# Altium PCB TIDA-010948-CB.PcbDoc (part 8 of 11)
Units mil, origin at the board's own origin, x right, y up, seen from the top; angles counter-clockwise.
Board outline 8100 x 8400 mil, 8 copper layers (L01 - TOP, L02 - GND, L03 - SIG, L04 - GND, L05 - PWR, L06 - SIG, L07 - GND, L08 - BOTTOM), stack 59.656 mil thick; 711 components, 572 nets, 2646 pads, 1325 vias.
Unrouted connection lines stored in the file: 988.
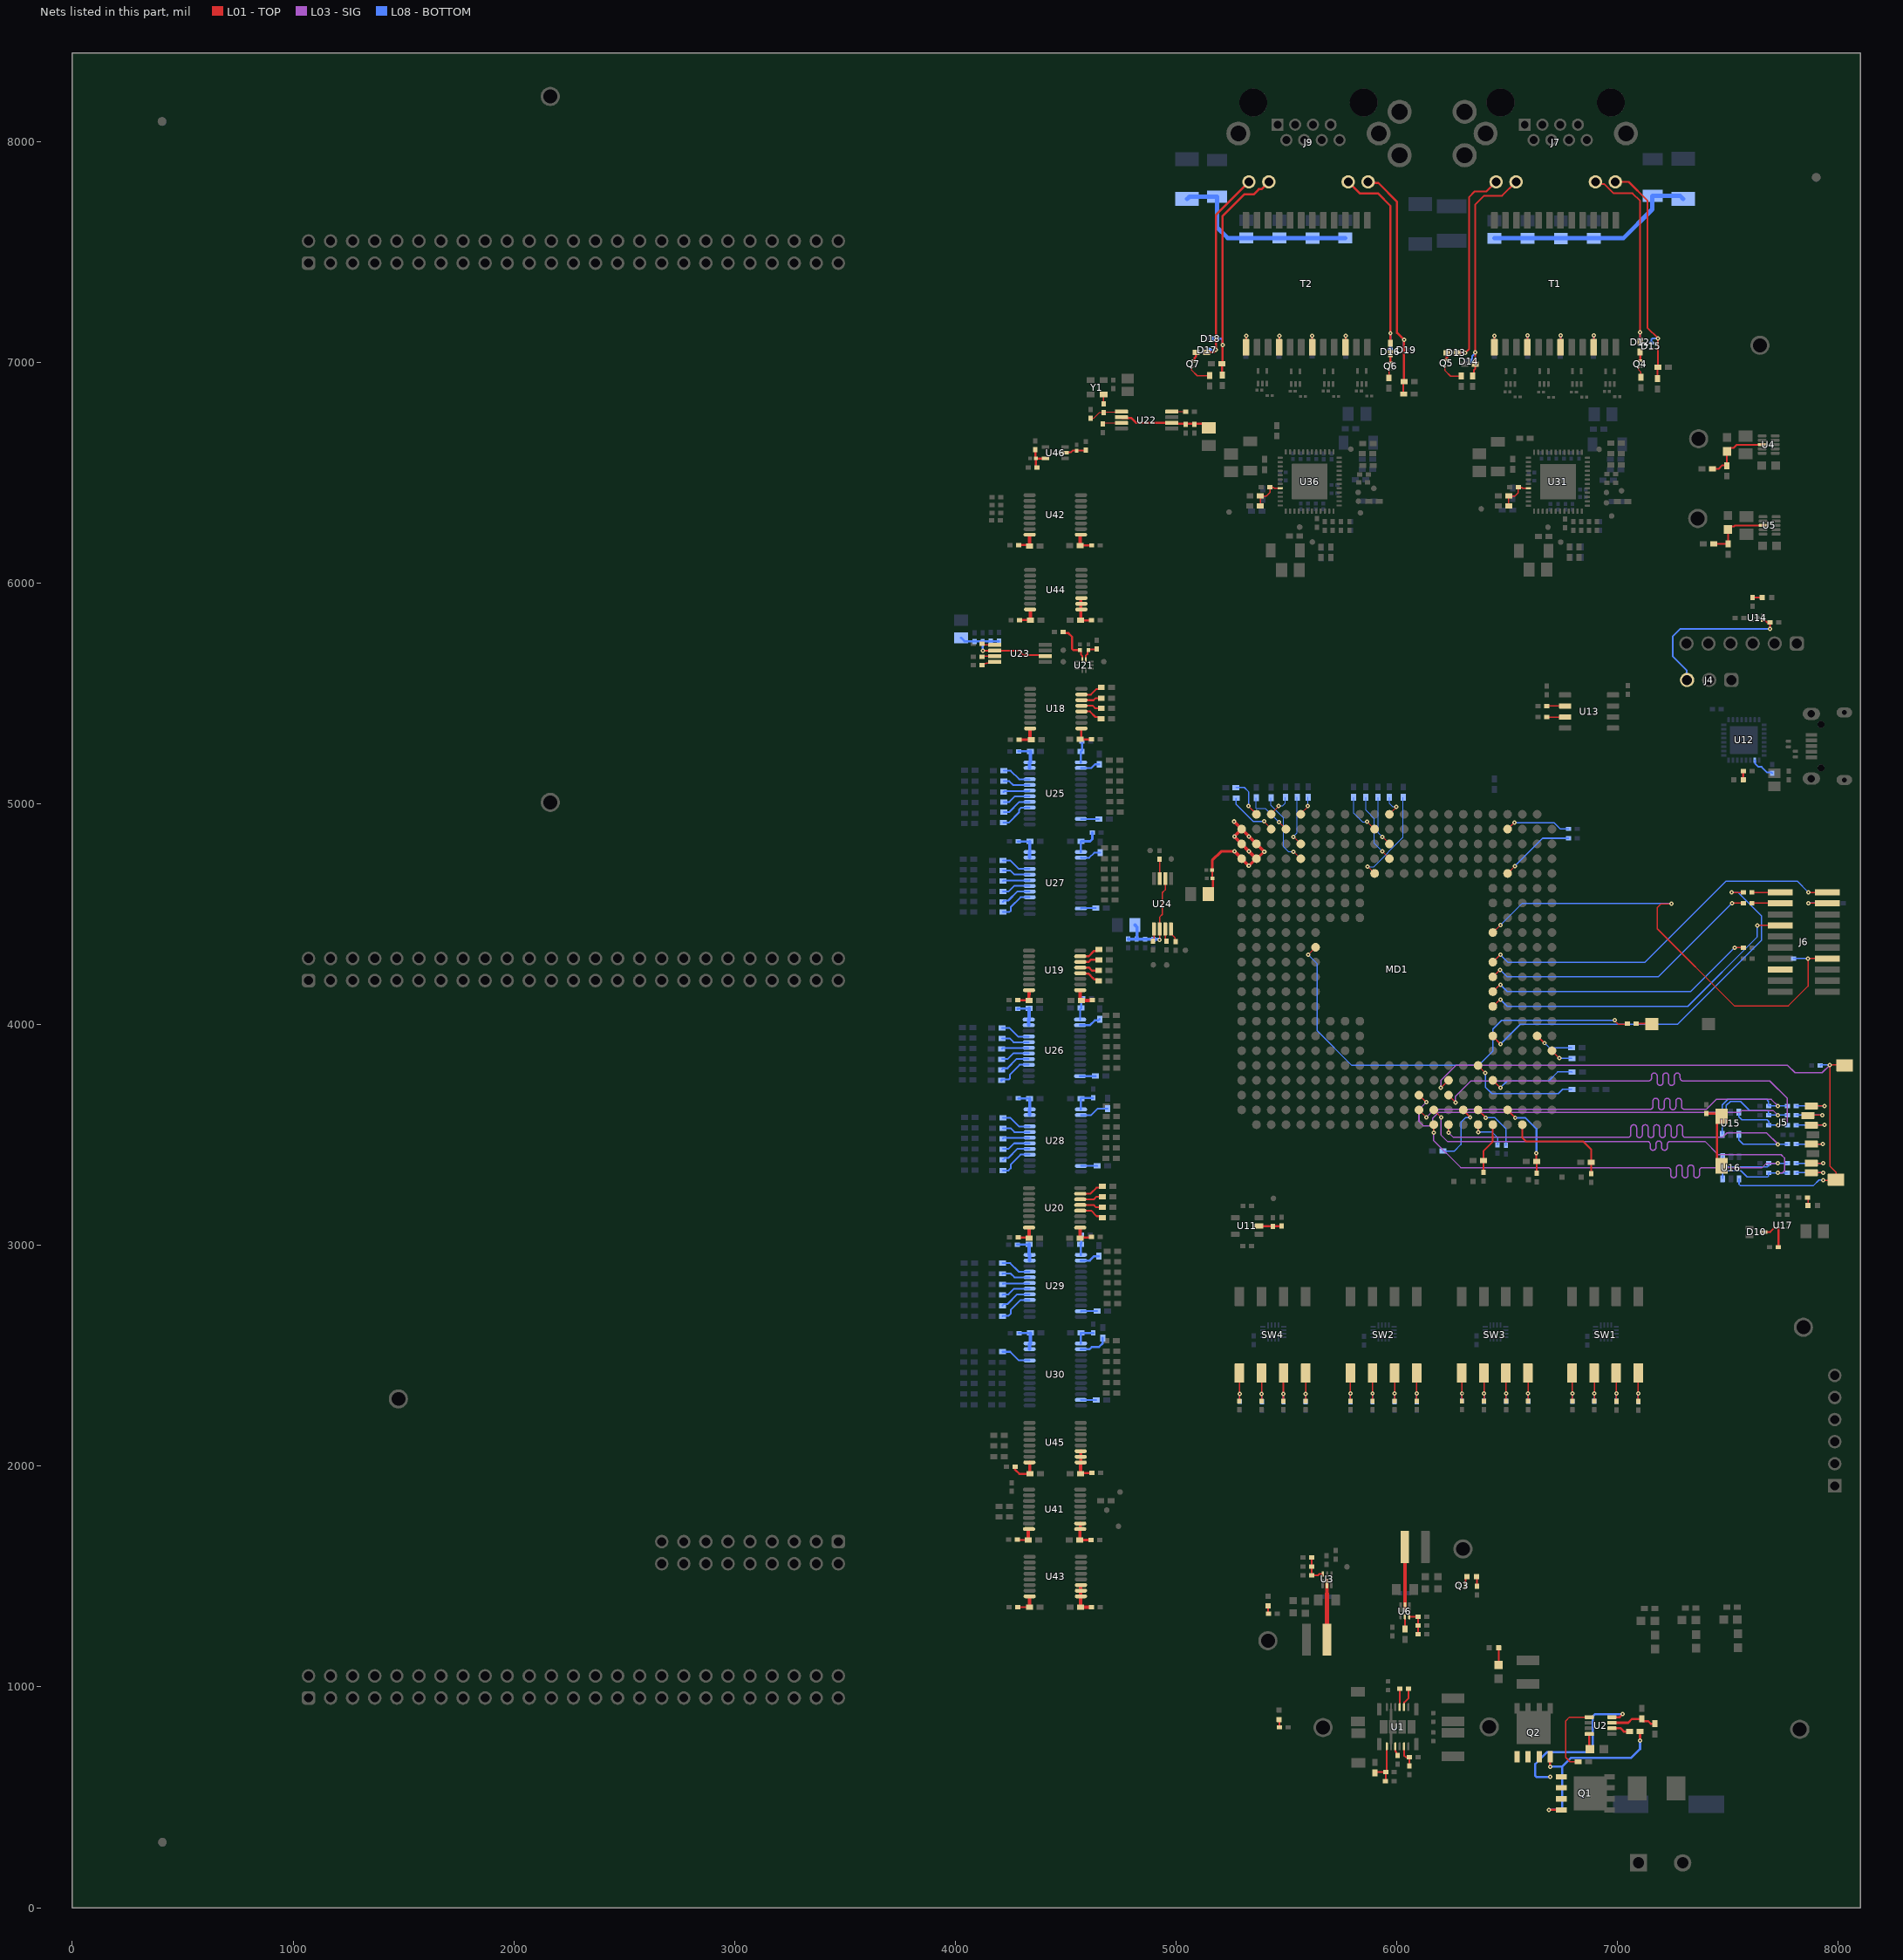
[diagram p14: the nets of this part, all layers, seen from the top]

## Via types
v1: diameter 19.68, hole 7.87, L01 - TOP to L08 - BOTTOM, 1310 vias
v2: diameter 20, hole 7.87, L01 - TOP to L08 - BOTTOM, tented both sides, 7 vias
v3: diameter 200, hole 144, L01 - TOP to L08 - BOTTOM, 6 vias
v4: diameter 20, hole 8, L01 - TOP to L08 - BOTTOM, tented both sides, 2 vias

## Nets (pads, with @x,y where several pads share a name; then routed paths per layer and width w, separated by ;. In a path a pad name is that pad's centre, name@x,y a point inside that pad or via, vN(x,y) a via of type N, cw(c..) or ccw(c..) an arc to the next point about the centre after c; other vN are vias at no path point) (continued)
JTAG_EMU1: J6.14 MD1.J18 R87.1 | length 2164.5
  L01 - TOP w6: MD1.J18@6435.04,4416.92 6435.48,4416.92 6469.56,4451 v1(6470,4451) ; v1(7244,4547) 7197,4547 7180,4530 7180,4434 7529,4085 7774,4085 7863,4174 v1(7863,4299) J6.14@7950.5,4299
  L08 - BOTTOM w6: v1(6470,4451) 6567,4548 v1@7235,4548 ; R87.1@7796.68,4299 v1(7863,4299)
JTAG_EMU_RSTn: J6.15
JTAG_TDI: J6.3 R93.2 | length 129.2
  L01 - TOP w5: R93.2@7608.69,4550 7736.5,4550 J6.3@7737.5,4549
JTAG_TDIS: J6.4 R84.2 | length 203.2
  L01 - TOP w5: v1(7865,4550) 7949.5,4550 J6.4@7950.5,4549
  L08 - BOTTOM w5: v1(7865,4550) R84.2@7982.31,4550
JTAG_TDO: J6.7 MD1.P18 | length 1510.9
  L01 - TOP w6: MD1.P18@6435.04,4082.28 6436.16,4082.28 6467.88,4114 v1(6469,4114) ; v1(7633,4449) J6.7@7737.5,4449
  L08 - BOTTOM w6: v1(6469,4114) 6500.5,4082.5 7318.5,4082.5 7633,4397 v1(7633,4449)
JTAG_TMS: J6.1 R94.2 | length 128.8
  L01 - TOP w6: R94.2@7608.69,4599 J6.1@7737.5,4599
JTAG_TRST#: J6.2 MD1.L18 | length 1716.3
  L01 - TOP w6: MD1.L18@6435.04,4283.06 6435.55,4283.06 6468.49,4316 v1(6469,4316) ; v1(7865,4599) J6.2@7950.5,4599
  L08 - BOTTOM w6: v1(6469,4316) 6502.5,4282.5 7124.5,4282.5 7492,4650 7814,4650 v1(7865,4599)
MMC1_CLK: MD1.AB15 R79.1 U15.4 | length 2289.2
  L01 - TOP w6: MD1.AB15@6234.25,3546.84 6234.63,3546.47 6234.63,3510.37 v1(6235,3510)
  L03 - SIG w6: v1(6235,3510) 6256,3489 7044.25,3489 7047.25,3489 ccw(c7047.25,3502) 7060.25,3502 7060.25,3533.37 cw(c7073.25,3533.37) 7086.25,3533.37 7086.25,3501.37 ccw(c7099.25,3501.37) 7112.25,3501.37 7112.25,3533.37 cw(c7125.25,3533.37) 7138.25,3533.37 7138.25,3501.37 ccw(c7151.25,3501.37) 7164.25,3501.37 7164.25,3533.37 cw(c7177.25,3533.37) 7190.25,3533.37 7190.25,3501.37 ccw(c7203.25,3501.37) 7216.25,3501.37 7216.25,3533.37 cw(c7229.25,3533.37) 7242.25,3533.37 7242.25,3501.37 ccw(c7255.25,3501.37) 7268.25,3501.37 7268.25,3533.37 cw(c7281.25,3533.37) 7294.25,3533.37 7294.25,3502 ccw(c7307.25,3502) 7307.25,3489 7369,3489 7475,3489 7496,3510 7675,3510 v1(7727,3458)
  L08 - BOTTOM w5: U15.4@7549.4,3502.8 7549.4,3478.6 7570,3458 v1(7727,3458) 7769.32,3458 R79.1@7770.32,3459
MMC1_CMD: MD1.Y15 R70.1 R78.1 U15.3 | length 2289.6
  L01 - TOP w6: MD1.Y15@6234.25,3680.7 6234.25,3679.23 6266,3647.48 v1(6266,3646)
  L03 - SIG w6: v1(6266,3646) 6266,3675.5 6335.5,3745 7137.62,3745 7140.62,3745 ccw(c7140.62,3758) 7153.62,3758 7153.62,3767.46 cw(c7166.62,3767.46) 7179.62,3767.46 7179.62,3737.78 ccw(c7192.62,3737.78) 7205.62,3737.78 7205.62,3767.46 cw(c7218.62,3767.46) 7231.62,3767.46 7231.62,3737.78 ccw(c7244.62,3737.78) 7257.62,3737.78 7257.62,3767.46 cw(c7270.62,3767.46) 7283.62,3767.46 7283.62,3758 ccw(c7296.62,3758) 7296.62,3745 7326,3745 7689.78,3745 7769.32,3665.46 7769.32,3560.75 7753.57,3545 v1(7726,3545)
  L08 - BOTTOM w5: U15.3@7549.4,3603.2 7549.4,3582.6 7564,3568 7678,3568 7685,3561 7685,3545.31 R70.1@7684.68,3545
  L08 - BOTTOM w6: R70.1@7684.68,3545 v1(7726,3545) R78.1@7769.32,3545
MMC1_DAT0: MD1.AB14 R71.1 R80.1 U16.1 | length 2290.9
  L01 - TOP w6: v1(6167,3510) 6167.16,3510.16 6167.16,3546.68 MD1.AB14@6167.32,3546.84
  L03 - SIG w6: v1@6164.38,3507.38 v1(6167,3510) 6167,3475 6289.98,3352.02 7166.52,3352.02 7228,3352.02 cw(c7228,3339.02) 7241,3339.02 7241,3319.44 ccw(c7254,3319.44) 7267,3319.44 7267,3351.3 cw(c7280,3351.3) 7293,3351.3 7293,3319.44 ccw(c7306,3319.44) 7319,3319.44 7319,3351.3 cw(c7332,3351.3) 7345,3351.3 7345,3319.44 ccw(c7358,3319.44) 7371,3319.44 7371,3339.02 cw(c7384,3339.02) 7384,3352.02 7387,3352.02 7655.02,3352.02 7675,3372 v1(7726,3372)
  L08 - BOTTOM w5: U16.1@7475.6,3402.2 7475.6,3378.4 7499.34,3354.66 7678.66,3354.66 7685,3361 7685,3371.69 R71.1@7684.68,3372
  L08 - BOTTOM w6: R71.1@7684.68,3372 v1(7726,3372) R80.1@7769.32,3372
MMC1_DAT1: MD1.AA14 R72.1 R81.1 U16.6 | length 2289.6
  L01 - TOP w6: MD1.AA14@6167.32,3613.73 v1(6201,3580)
  L03 - SIG w6: v1(6201,3580) 6201,3499 6229,3471 7074,3471 7134.85,3471 cw(c7134.85,3458) 7147.85,3458 7147.85,3443.68 ccw(c7160.85,3443.68) 7173.85,3443.68 7173.85,3459.69 cw(c7186.85,3459.69) 7199.85,3459.69 7199.85,3443.68 ccw(c7212.85,3443.68) 7225.85,3443.68 7225.85,3458 cw(c7238.85,3458) 7238.85,3471 7241.85,3471 7396,3471 7456,3411 7741,3411 7756,3396 7756,3338 7746,3328 v1(7726,3328)
  L08 - BOTTOM w5: U16.6@7475.6,3301.8 7475.6,3329.6 7483,3337 7560,3337 7587,3310 7680.07,3310 7683,3312.93 7683,3326.31 R72.1@7684.68,3328
  L08 - BOTTOM w6: R72.1@7684.68,3328 v1(7726,3328) R81.1@7769.32,3328
MMC1_DAT2: MD1.AA13 R68.1 R74.1 U15.1 | length 2289
  L01 - TOP w6: MD1.AA13@6100.39,3613.77 6100.39,3613.69 6134,3580.08 v1(6134,3580)
  L03 - SIG w6: v1(6134,3580) 6170,3616 7144,3616 7147,3616 ccw(c7147,3629) 7160,3629 7160,3653.24 cw(c7173,3653.24) 7186,3653.24 7186,3627.41 ccw(c7199,3627.41) 7212,3627.41 7212,3653.24 cw(c7225,3653.24) 7238,3653.24 7238,3627.41 ccw(c7251,3627.41) 7264,3627.41 7264,3653.24 cw(c7277,3653.24) 7290,3653.24 7290,3629 ccw(c7303,3629) 7303,3616 7369.62,3616 7402,3616 7447,3661 7697,3661 v1(7726,3632)
  L08 - BOTTOM w5: U15.1@7474.6,3603.2 7474.6,3636.6 7500,3662 7675,3662 7684.68,3652.31 R68.1@7684.68,3632
  L08 - BOTTOM w6: R68.1@7684.68,3632 v1(7726,3632) R74.1@7769.32,3632
MMC1_DAT3: MD1.Y13 R69.1 R76.1 U15.6 | length 2289.3
  L01 - TOP w6: MD1.Y13@6100.39,3680.7 6101.35,3680.7 6133.05,3649 v1(6134,3649)
  L03 - SIG w6: v1(6134,3649) 6100.39,3615.39 6100.39,3560.61 6120,3541 6147,3541 6162,3556 6162,3574.73 6189.27,3602 7554.7,3602 7563.7,3611 7705,3611 v1(7726,3590)
  L08 - BOTTOM w5: U15.6@7474.6,3502.8 7474.6,3558.86 7492.93,3577.19 7492.93,3633.93 7511,3652 7557,3652 7598,3611 7680,3611 7684.68,3606.31 R69.1@7684.68,3590
  L08 - BOTTOM w6: R69.1@7684.68,3590 v1(7726,3590) R76.1@7769.32,3590
NetC9_1: C9.1 R3.1 R6.2 U1.10 | length 210.1
  L01 - TOP w8: R3.1@5901,610.38 5905.62,615 C9.1@5949.31,615 ; R6.2@5949.31,573 C9.1@5949.31,615 ; U1.10@5954.26,730.83 5953.34,729.91 5953.34,619.02 C9.1@5949.31,615
NetC11_2: C11.2 U2.4 | length 68.7
  L01 - TOP w8: U2.4@6871.82,786.61 6871.82,721.69 C11.2@6874.5,719
NetC14_2: C14.2 R16.1 R17.2 U3.3 | length 128.4
  L01 - TOP w8: C14.2@5614.69,1582.5 5614.69,1542 R17.2@5614.69,1506 5643.96,1506 5649.55,1511.59 U3.3@5664.31,1511.59
NetC16_2: C16.2 R15.1 R18.2 U4.8 | length 308.9
  L01 - TOP w8: R15.1@7430.22,6517.26 7458.6,6517.26 7474.6,6533.26 7494.22,6533.26 R18.2@7495.6,6531.89 7495.6,6594.77 C16.2@7496.6,6595.77 7496.6,6596.56 7511.3,6611.26 7524.6,6611.26 7538.6,6625.26 7653.07,6625.26 U4.8@7655.07,6627.26
NetC23_2: C23.2 R20.1 R23.2 U5.8 | length 299.8
  L01 - TOP w8: R20.1@7436.23,6178.05 7500.23,6178.05 R23.2@7501.61,6176.67 7501.61,6240.55 C23.2@7499.61,6242.55 7514.1,6257.05 7527.61,6257.05 7531.61,6261.05 U5.8@7659.08,6261.05
NetC25_2: C25.2 R24.1 R25.2 U6.3 | length 119.3
  L01 - TOP w8: U6.3@6056.69,1318.41 6056.89,1318.2 6096.11,1318.2 R25.2@6096.31,1318 ; C25.2@6096.81,1238.5 R25.2@6096.81,1318
NetC29_1: C29.1 R59.2 U11.2 | length 104
  L01 - TOP w10: U11.2@5376.13,3088 5376.98,3087.16 5437.16,3087.16 C29.1@5438,3086.31 5438.5,3086.81 5478.5,3086.81 R59.2@5479,3087.31
NetC40_1: C40.1 J4.3 U14.1 | length 747.7
  L01 - TOP w8: U14.1@7654.13,5830.41 7667.59,5830.41 7677,5821 7690.32,5821 C40.1@7690.66,5821.34 ; v1(7690,5793) 7690.66,5793.66 C40.1@7690.66,5821.34 ; C40.1@7691.32,5822 C40.1@7690.66,5821.34
  L08 - BOTTOM w8: J4.3@7315,5561 7312.52,5563.48 7312.52,5605.48 7251,5667 7251,5759 7285,5793 v1(7690,5793)
NetC41_2: C41.2 MD1.AB20 R77.2 | length 503.9
  L01 - TOP w8: MD1.AB20@6568.9,3546.84 6568.9,3486.77 6584.67,3471 6844.06,3471 6880.62,3434.44 C41.2@6880.62,3377 6881,3376.62 R77.2@6881,3324.19
NetC42_2: C42.2 MD1.AA19 R75.2 | length 371
  L01 - TOP w8: MD1.AA19@6501.97,3613.77 6501.97,3612.4 6536,3578.37 v1(6536,3577) ; v1(6632.63,3417.31) 6632.63,3381.69 6633.63,3380.69 R75.2@6633.63,3327
  L08 - BOTTOM w8: v1@6534.63,3575.63 v1(6536,3577) 6583.15,3577 6632.75,3527.4 6632.75,3417.43 v1(6632.63,3417.31)
NetC43_2: C43.2 MD1.AB18 R73.2 | length 234.5
  L01 - TOP w8: R73.2@6392,3330.19 6392,3384.88 C43.2@6392.12,3385 6392.12,3426.62 6435.04,3469.54 MD1.AB18@6435.04,3546.84
NetC47_2: C47.2 R241.1 U18.1 | length 95.7
  L01 - TOP w10: C47.2@4566.12,5291.5 4566.87,5292.25 4615.56,5292.25 R241.1@4616.31,5293 ; C47.2@4571.14,5296.52 U18.1@4571.14,5341.43
NetC48_1: C48.1 R268.1 U18.16 | length 101
  L01 - TOP w12: R268.1@4289.69,5289.5 4289.94,5289.75 4343.13,5289.75 C48.1@4343.38,5290
  L01 - TOP w15: C48.1@4338.86,5294.31 U18.16@4338.86,5341.43
NetC49_2: C49.2 R276.1 U19.1 | length 96.9
  L01 - TOP w15: U19.1@4565.72,4155.51 4565.72,4113.8 C49.2@4570.3,4109.22 ; C49.2@4570.72,4109.65 R276.1@4619.46,4109.65
NetC50_1: C50.1 R281.1 U19.16 | length 98.7
  L01 - TOP w10: R281.1@4282.69,4111 4283.69,4110 4332.88,4110 4333.63,4109.25 C50.1@4333.88,4109
  L01 - TOP w15: C50.1@4333.63,4109.25 U19.16@4333.86,4155.93
NetC51_2: C51.2 R291.1 U20.1 | length 100.7
  L01 - TOP w10: C51.2@4565.08,3033 4565.61,3033.54 4567.32,3035.25 4614.57,3035.25 R291.1@4616.81,3037.5
  L01 - TOP w15: C51.2@4565.61,3033.54 4565.61,3079.9 U20.1@4566.14,3080.43
NetC52_1: C52.1 R317.1 U20.16 | length 100.2
  L01 - TOP w10: R317.1@4284.19,3037 4286.44,3034.75 4332.63,3034.75 4334.37,3033.01 C52.1@4334.88,3032.5
  L01 - TOP w15: U20.16@4333.86,3080.43 4334.37,3079.92 C52.1@4334.37,3033.01
NetC53_1: C53.1 C54.1 L3.1 U22.2 U22.6 | length 415.5
  L01 - TOP w10: U22.2@4752.33,6750.8 4755.08,6748.04 4796.85,6748.04 4819.69,6725.2 U22.6@4980.67,6725.2 4984.38,6721.5 5129.5,6721.5 L3.1@5148,6703
NetC55_1: C55.1 R318.1 U21.7 | length 190.3
  L01 - TOP w8: C55.1@4564.5,5696.01 4568.77,5691.74 4568.77,5676.23 4574.71,5670.29 4574.71,5651.82 U21.7@4574.77,5651.76
  L01 - TOP w10: R318.1@4488.19,5777.5 4493.03,5772.66 4512.34,5772.66 4529,5756 4529,5701.87 4534.86,5696.01 C55.1@4564.5,5696.01
NetC56_2: C56.2 R319.1 U21.6 | length 88.6
  L01 - TOP w8: U21.6@4590.52,5651.76 4590.58,5651.82 4590.58,5670.08 4598.73,5678.23 4598.73,5691.74 C56.2@4603,5696.01 4605.65,5698.66 4637.35,5698.66 R319.1@4640,5701.31
NetC59_1: C59.1 C60.1 C61.1 C62.1 L4.1 U23.2 U23.6 | length 510.9
  L01 - TOP w8: v1(4124,5694) 4124.15,5694.15 4178.68,5694.15 U23.6@4178.83,5694.3 4287.2,5694.3 4308.5,5673 4402.88,5673 U23.2@4407.17,5668.7
  L08 - BOTTOM w8: v1(4124,5694) v1(4124,5694) 4123.96,5732.78 C61.1@4124,5732.81
  L08 - BOTTOM w10: L4.1@4026,5752 4041.69,5736.31 4086.5,5736.31 4121.75,5736.31 C62.1@4159.77,5736.31 ; C62.1@4159.77,5736.46 C59.1@4197.65,5736.46
NetC63_1: C63.1 C64.1 C65.1 C66.1 L5.1 U24.2 U24.6 | length 491.9
  L01 - TOP w6: v1(4925.5,4384.5) 4925.35,4384.65 4925.35,4432.68 U24.6@4925.2,4432.83 4925.5,4433.12 4925.5,4486.5 4938,4499 4938,4598 4950.8,4610.8 U24.2@4950.8,4661.17
  L08 - BOTTOM w15: C64.1@4784.54,4387.09 4784.75,4386.88 4860.64,4386.88 C66.1@4860.85,4386.66 ; L5.1@4814,4450.5 4823.2,4441.3 C65.1@4823.2,4387.38 ; C66.1@4865.16,4386.33 4922.4,4386.33 4924.23,4384.5 v1(4925.5,4384.5)
NetC79_2: C79.2 R322.1 U25.1 | length 96.2
  L08 - BOTTOM w10: U25.1@4569.14,5187.75 4569.14,5237.02 C79.2@4570.12,5238 4573.76,5241.64 R322.1@4573.76,5282.03
NetC80_2: C80.2 R320.1 U26.1 | length 103.2
  L08 - BOTTOM w8: U26.1@4565.14,4022.75 4565.14,4070.02 C80.2@4570.12,4075
  L08 - BOTTOM w10: C80.2@4570.12,4075 R320.1@4570.12,4113.08 ; R320.1@4570.15,4113.11 4570.15,4115.08 4575,4119.92 R320.1@4576.96,4119.92
NetC93_2: C93.2 R326.1 U27.1 | length 134
  L08 - BOTTOM w10: U27.1@4569.14,4781.83 4569.14,4829.55 C93.2@4569.78,4830.19 4610.69,4830.19 4620.81,4840.31 R326.1@4620.81,4870.5
NetC94_2: C94.2 R324.1 U28.1 | length 107
  L08 - BOTTOM w10: U28.1@4569.14,3615.75 4569.14,3664.98 C94.2@4568.62,3665.5 4570.03,3666.91 4623.09,3666.91 R324.1@4624.5,3668.31
NetC101_2: C101.2 R328.1 U29.1 | length 92.9
  L08 - BOTTOM w10: U29.1@4569.14,2957.25 4569.14,3003.37 C101.2@4567.3,3005.21 4570.98,3008.9 R328.1@4570.98,3047.9
NetC108_2: C108.2 R330.1 U30.1 | length 103.3
  L08 - BOTTOM w10: U30.1@4569.14,2555.75 4569.14,2602.54 C108.2@4569.71,2603.11 4570,2603.4 4624.9,2603.4 R330.1@4625.19,2603.68
NetC112_1: C112.1 R323.1 U25.23 U25.24 | length 131
  L08 - BOTTOM w10: R323.1@4286.19,5237.5 4286.44,5237.25 4339.63,5237.25 C112.1@4339.88,5237
  L08 - BOTTOM w15: U25.23@4336.86,5162.16 U25.24@4336.86,5187.75 4338.62,5187.75 4339.88,5189 C112.1@4339.88,5237
NetC120_1: C120.1 R321.1 U26.23 U26.24 | length 129.4
  L08 - BOTTOM w10: R321.1@4282.19,4071.5 4282.94,4072.25 4333.63,4072.25 C120.1@4334.38,4073
  L08 - BOTTOM w15: U26.23@4332.86,3997.16 U26.24@4332.86,4022.75 4333.12,4022.75 4334.38,4024 C120.1@4334.38,4073
NetC126_1: C126.1 R327.1 U27.23 U27.24 | length 125.9
  L08 - BOTTOM w10: R327.1@4284.69,4830 4284.93,4829.75 4336.61,4829.75 C126.1@4337.15,4829.22
  L08 - BOTTOM w15: U27.23@4336.86,4756.24 U27.24@4336.86,4781.83 4337.15,4782.12 C126.1@4337.15,4829.22
NetC132_1: C132.1 R325.1 U28.23 U28.24 | length 126.6
  L08 - BOTTOM w10: R325.1@4285.69,3666 4286.13,3665.56 4336.46,3665.56 C132.1@4336.9,3665.11
  L08 - BOTTOM w15: U28.23@4336.84,3590.18 4336.84,3615.73 U28.24@4336.86,3615.75 C132.1@4336.9,3665.11
NetC133_1: C133.1 T1.1 | length 96
  L01 - TOP w8: T1.1@6442,7067.5 6442.5,7068 v1(6442.5,7120.5)
  L08 - BOTTOM w8: C133.1@6441.5,7078.12 6442,7078.62 6442,7120 v1(6442.5,7120.5)
NetC134_1: C134.1 T1.4 | length 97.3
  L01 - TOP w8: T1.4@6592,7067.5 6592.5,7068 v1(6592.5,7121)
  L08 - BOTTOM w8: C134.1@6592,7077.62 6592.25,7077.87 6592.25,7120.75 v1(6592.5,7121)
NetC136_2: C136.2 D14.2 J7.10 R240.1 | length 1055.9
  L01 - TOP w8: R240.1@6343,6937.12 6349.87,6943.99 6349.87,6964.87 6355.5,6970.5 6355.5,6990.62 C136.2@6354.62,6991.5 6354.62,7713.62 6395,7754 6477.07,7754 J7.10@6540.08,7817.01
  L08 - BOTTOM w8: D14.2@6339.8,7005 6341.97,7007.18 6341.97,7028.81 6354.5,7041.34 v1(6354.5,7044.5)
NetC137_1: C137.1 T1.7 | length 96.3
  L01 - TOP w8: T1.7@6742,7067.5 v1(6742,7121)
  L08 - BOTTOM w8: C137.1@6741,7078.62 6741.5,7079.12 6741.5,7120.5 v1(6742,7121)
NetC138_1: C138.1 R246.2 R305.2 U31.20 | length 166
  L01 - TOP w6: R305.2@6506.69,6349.06 R305.2@6507.12,6349.5 ; R305.2@6506.98,6349.53 6506.98,6394.03 6535.03,6394.03 6550.04,6409.04 6550.04,6433.03 6565.79,6433.03 6569.35,6429.47 U31.20@6596.14,6429.47
NetC139_2: C139.2 D15.2 J7.12 R244.2 | length 1055.9
  L01 - TOP w8: J7.12@6990.08,7817.01 7050.49,7817.01 7135,7732.5 7135,7156.5 v1(7183.38,7108.12) C139.2@7183.38,6977.5 7181.5,6975.62 R244.2@7181.5,6926.62
  L08 - BOTTOM w8: D15.2@7153,7086.5 7153,7103.44 7157.69,7108.12 v1(7183.38,7108.12)
NetC140_1: C140.1 T1.10 | length 97.6
  L01 - TOP w8: T1.10@6892,7067.5 v1(6892,7121)
  L08 - BOTTOM w8: C140.1@6891.5,7077.12 6891.75,7077.37 6891.75,7120.75 v1(6892,7121)
NetC141_1: C141.1 R229.2 R231.2 R245.2 R248.2 R249.2 | length 974.7
  L08 - BOTTOM w20: R229.2@6443,7561.5 7026,7561.5 7157,7692.5 7157,7752.32 C141.1@7159,7754.32 7283.13,7754.32 R249.2@7297,7740.45
NetC154_1: C154.1 R329.1 U29.23 U29.24 | length 130.2
  L08 - BOTTOM w10: R329.1@4280.19,3003 4281.22,3004.04 4333.02,3004.04 C154.1@4334.06,3005.08
  L08 - BOTTOM w15: C154.1@4334.06,3005.08 4334.06,2958.5 4335.32,2957.25 U29.24@4336.86,2957.25 U29.23@4336.86,2931.66
NetC162_1: C162.1 R331.1 U30.23 U30.24 | length 127
  L08 - BOTTOM w10: R331.1@4288.19,2602.5 4288.44,2602.75 4339.63,2602.75 C162.1@4339.88,2603
  L08 - BOTTOM w15: U30.23@4336.86,2530.16 U30.24@4336.86,2555.75 4338.62,2555.75 4339.88,2557 C162.1@4339.88,2603
NetC168_1: C168.1 C174.1 L12.1 MD1.B1 MD1.C1 MD1.C2 MD1.D1 MD1.D2 | length 853.4
  L01 - TOP w8: C174.1@5163.49,4700 5164.22,4699.27 5164.22,4663.27 C168.1@5164.95,4662.54 ; v2@5263,4919.84 v2(5263,4920)
  L01 - TOP w10: L12.1@5146.5,4590.5 5166.5,4610.5 5166.5,4645.58 5167.71,4646.79 5167.71,4659.78 C168.1@5164.95,4662.54
  L01 - TOP w12: C174.1@5163.49,4700 5163.49,4743.74 5204.01,4784.26 v2(5265,4784.26) ; v2(5329,4720) 5330.8,4720 5362.37,4751.57 MD1.D2@5364.17,4751.57 5366.4,4751.57 5397.84,4783 v2(5400,4783)
  L01 - TOP w15: v2(5263,4920) v2(5400,4783) ; v2(5265,4784.26) 5265,4784.13 5329,4720.13 v2(5329,4720) ; MD1.B1@5297.24,4885.43 5297.24,4885.34 5264,4852.09 v4(5264,4852) 5264,4851.87 5364.17,4751.7 MD1.D2@5364.17,4751.57
  L01 - TOP w20: v4@5264,4851.74 v4@5264,4851.87 ; v2@5330.49,4785.25 v2@5330.71,4785.03
  other v2: 5330.27,4785.03
  other v4: 5330.27,4851.96
NetC175_1: C175.1 T2.1 | length 92.7
  L01 - TOP w8: T2.1@5317,7067.5 5318,7068.5 v1(5318,7119)
  L08 - BOTTOM w8: C175.1@5317,7078.62 5317.5,7079.12 5317.5,7118.5 v1(5318,7119)
NetC176_1: C176.1 T2.4 | length 92.7
  L01 - TOP w8: T2.4@5467,7067.5 5468,7068.5 v1(5468,7119)
  L08 - BOTTOM w8: C176.1@5467,7078.62 5467.5,7079.12 5467.5,7118.5 v1(5468,7119)
NetC178_2: C178.2 D18.2 J9.10 R280.1 | length 1064.8
  L01 - TOP w10: C178.2@5207.12,6994 5210.12,6997 5210.12,7661.12 5309,7760 5351,7760 5375,7784 5387.07,7784 J9.10@5420.08,7817.01 ; R280.1@5209,6941.12 C178.2@5209,6994
  L08 - BOTTOM w10: D18.2@5169.22,7106.61 5204.64,7106.61 5210.5,7100.75 v1(5210.5,7078) v1@5207.88,7078
NetC179_1: C179.1 T2.7 | length 89.9
  L01 - TOP w8: T2.7@5617,7067.5 v1(5617,7119)
  L08 - BOTTOM w8: C179.1@5617,7080.62 v1(5617,7119)
NetC180_1: C180.1 R260.2 R286.2 U36.20 | length 166.8
  L01 - TOP w6: R260.2@5381.12,6349 5382.12,6350 R286.2@5382.12,6394.5 5410.18,6394.5 5425.19,6409.51 C180.1@5425.19,6433.5 5440.93,6433.5 5444.49,6429.94 U36.20@5471.28,6429.94
NetC181_2: C181.2 D19.2 J9.12 R284.2 | length 1100.7
  L01 - TOP w8: R284.2@6029,6856.62 6029,6909.12 C181.2@6032.38,6912.5
  L01 - TOP w10: J9.12@5870.08,7817.01 5874.68,7812.41 5915.59,7812.41 6001.5,7726.5 6001.5,7133.5 v1(6032.38,7102.62) C181.2@6032.38,6912.5
  L08 - BOTTOM w10: D19.2@6032.2,7055 6032.29,7055.09 6032.29,7102.54 v1(6032.38,7102.62)
NetC182_1: C182.1 T2.10 | length 92.3
  L01 - TOP w8: T2.10@5767,7067.5 5768,7068.5 v1(5768,7119)
  L08 - BOTTOM w8: C182.1@5768,7078.62 v1(5768,7119)
NetC183_1: C183.1 R269.2 R271.2 R285.2 R287.2 R288.2 | length 879.7
  L08 - BOTTOM w20: R288.2@5050,7739.45 5060.87,7750.32 C183.1@5186,7750.32 5186,7611 5234,7563 R269.2@5318,7563 R271.2@5468,7563 R287.2@5766,7563
NetC193_2: C193.2 R332.1 U41.1 U41.2 | length 127.5
  L01 - TOP w10: C193.2@4564.12,1665.5 R332.1@4615.31,1665.5
  L01 - TOP w15: C193.2@4564.12,1665.5 4564.12,1713.67 4565.38,1714.93 U41.1@4566.14,1714.93 U41.2@4566.14,1740.52
NetC194_1: C194.1 R333.1 U41.16 | length 102.4
  L01 - TOP w8: R333.1@4280.19,1667 4280.86,1666.32 4330.14,1666.32 C194.1@4330.82,1665.64
  L01 - TOP w15: C194.1@4330.82,1666.07 4330.82,1713.67 4332.07,1714.93 U41.16@4333.86,1714.93
NetC195_2: C195.2 R334.1 U42.1 | length 104.1
  L01 - TOP w10: C195.2@4565.62,6170 4565.87,6170.25 4617.56,6170.25 R334.1@4617.81,6170.5
  L01 - TOP w15: C195.2@4565.62,6170 4565.62,6217.68 4566.88,6218.93 U42.1@4569.14,6218.93
NetC196_1: C196.1 R335.1 U42.16 | length 104.2
  L01 - TOP w10: R335.1@4286.19,6172 4331.86,6172 C196.1@4336.38,6167.48
  L01 - TOP w15: C196.1@4336.38,6167 4336.86,6167.48 U42.16@4336.86,6218.93
NetC197_2: C197.2 R336.1 U43.1 U43.2 U43.3 | length 150.8
  L01 - TOP w15: U43.3@4569.14,1461.61 4568.38,1461.61 4567.12,1460.36 C197.2@4567.12,1362 4567.37,1361.75 4616.56,1361.75 R336.1@4616.81,1361.5
NetC198_1: C198.1 R337.1 U43.16 | length 101.5
  L01 - TOP w8: R337.1@4283.19,1361 4283.5,1361.31 4335.88,1361.31 C198.1@4336.19,1361.62
  L01 - TOP w15: C198.1@4336.52,1362.31 4336.52,1410.1 U43.16@4336.86,1410.43
NetC199_2: C199.2 R339.1 U44.1 U44.2 U44.3 | length 151.5
  L01 - TOP w10: C199.2@4568.12,5831.5 4568.37,5831.25 4617.06,5831.25 R339.1@4617.31,5831
  L01 - TOP w15: C199.2@4568.12,5831.75 4568.12,5930.36 4569.38,5931.61 U44.3@4571.14,5931.61
NetC200_1: C200.1 R340.1 U44.16 | length 99.4
  L01 - TOP w10: R340.1@4291.69,5832.3 4291.98,5832 4338.56,5832 C200.1@4340.01,5830.55
  L01 - TOP w15: U44.16@4338.86,5880.43 4340.01,5879.28 C200.1@4340.01,5830.55
NetC201_2: C201.2 R341.1 U45.1 U45.2 U45.3 | length 156.6
  L01 - TOP w10: C201.2@4566.87,1965.75 C201.2@4566.62,1966 4567.38,1966.76 4568.87,1968.25 4617.06,1968.25 R341.1@4619.31,1970.5
  L01 - TOP w15: C201.2@4567.38,1966.76 4567.38,2016.17 U45.1@4568.14,2016.93 U45.2@4568.14,2042.52 U45.3@4568.14,2068.11
NetC202_1: C202.1 R342.1 U45.16 | length 140.3
  L01 - TOP w10: R342.1@4270.19,1998 4271.04,1997.15 4271.04,1984.22 4289.76,1965.5 4338.52,1965.5 C202.1@4339.17,1966.16
  L01 - TOP w15: U45.16@4335.86,2016.93 4336.26,2016.93 4337.52,2015.68 C202.1@4337.52,1967.82
NetC203_1: C203.1 R300.1 R338.1 U46.5 | length 128.5
  L01 - TOP w10: R300.1@4362,6604.31 4363.25,6603.07 4363.25,6565.75 C203.1@4364.49,6564.5 ; R338.1@4370.33,6524.08 4369.33,6524.08 4364.49,6528.92 C203.1@4364.49,6564.5 ; U46.5@4408.71,6564.41 4408.66,6564.45 C203.1@4364.49,6564.5 C203.1@4364.49,6564.5
NetC204_1: C204.1 R343.1 U46.2 | length 98.4
  L01 - TOP w8: U46.2@4497.29,6590 4498.79,6591.5 4522.5,6591.5 4531.01,6600.01 C204.1@4549.5,6600.01 4550.15,6600.66 4590.35,6600.66 R343.1@4591,6601.31
NetD1_2: D1.2 R1.1 | length 77.8
  L01 - TOP w8: R1.1@6461,1099.5 6461.65,1100.15 D1.2@6461.65,1177
NetD2_2: D2.2 R7.1 | length 35.9
  L01 - TOP w8: D2.2@5466.69,852.35 5467.34,851.69 5467.34,817.66 R7.1@5468,817
NetD4_2: D4.2 R14.1 | length 36.9
  L01 - TOP w8: D4.2@5417,1367.35 5417.66,1366.69 5417.66,1331.66 R14.1@5418.31,1331
NetD5_1: D5.1 Q3.3 | length 43.5
  L01 - TOP w8: Q3.3@6309.8,1459.84 6312.69,1462.73 6312.69,1494.84 D5.1@6317.85,1500
NetD5_2: D5.2 R21.1 | length 43.8
  L01 - TOP w8: D5.2@6362.33,1500 6362.33,1457.2 R21.1@6363,1456.53
NetD8_2: D8.2 R64.1 | length 40.2
  L01 - TOP w10: D8.2@7569.26,5109.2 7569.79,5109.72 7569.79,5148.47 R64.1@7570.32,5149
NetD9_2: D9.2 R67.1 | length 43.5
  L01 - TOP w8: R67.1@7612,5934.69 7612.16,5934.84 7655.19,5934.84 D9.2@7655.35,5935
NetD10_3: D10.3 R88.1 U17.C2 | length 164.2
  L01 - TOP w8: D10.3@7661.5,3061 7692,3061 7711.16,3080.16 7728.91,3080.16 7729.11,3079.96 7729.11,2993.43 R88.1@7727.68,2992
NetD11_2: D11.2 R91.1 | length 37.5
  L01 - TOP w6: R91.1@7860.68,3217 7862.82,3214.86 D11.2@7862.82,3180.4
NetD12_2: D12.2 J7.11 R239.2 | length 907.3
  L01 - TOP w8: J7.11@6899.92,7817.01 6910.07,7806.86 6940.41,7806.86 6981.78,7765.5 7068,7765.5 7102.5,7731 v1(7102.5,7135) R239.2@7102.5,7093.62
  L08 - BOTTOM w8: D12.2@7102.5,7103.3 v1(7102.5,7135)
NetD13_2: D13.2 J7.9 R232.2 | length 928.6
  L01 - TOP w8: R232.2@6273.62,7043 v1(6310.5,7043) 6328,7060.5 6328,7748.5 6353,7773.5 6406.41,7773.5 J7.9@6449.92,7817.01
  L08 - BOTTOM w8: D13.2@6281.8,7043 v1(6310.5,7043)
NetD16_2: D16.2 J9.11 R279.2 | length 930.5
  L01 - TOP w10: J9.11@5779.92,7817.01 5831.93,7765 5914,7765 5971,7708 v1(5971,7132.5) R279.2@5971,7086.62
  L08 - BOTTOM w10: D16.2@5970.5,7059.8 5970.75,7060.05 5970.75,7132.25 v1(5971,7132.5)
NetD17_2: D17.2 J9.9 R272.2 | length 896.4
  L01 - TOP w10: R272.2@5138.62,7045.5 5169.37,7045.5 v1(5180.5,7056.63) 5180.5,7667.59 J9.9@5329.92,7817.01
  L08 - BOTTOM w8: D17.2@5153.3,7055.5 5153.86,7056.06 5179.94,7056.06 v1(5180.5,7056.63)
NetJ5_1: J5.1 R74.2 | length 190.1
  L01 - TOP w6: J5.1@7877.43,3631.54 7877.89,3632 v1(7938,3632)
  L08 - BOTTOM w6: R74.2@7808.69,3632 v1(7938,3632)
NetJ5_2: J5.2 R76.2 | length 186.4
  L01 - TOP w6: J5.2@7861.68,3588.23 7863.45,3590 v1(7928,3590)
  L08 - BOTTOM w6: R76.2@7808.69,3590 v1(7928,3590)
NetJ5_3: J5.3 R78.2 | length 188.8
  L01 - TOP w6: J5.3@7877.43,3544.92 7878.5,3546 v1(7937,3546)
  L08 - BOTTOM w6: R78.2@7808.69,3545 7809.69,3546 v1(7937,3546)
NetJ5_5: J5.5 R79.2 | length 173.2
  L01 - TOP w6: J5.5@7877.43,3458.31 7878.12,3459 v1(7930,3459)
  L08 - BOTTOM w6: R79.2@7809.69,3459 v1(7930,3459)
NetJ5_7: J5.7 R80.2 | length 178
  L01 - TOP w6: J5.7@7877.43,3371.69 7877.73,3372 v1(7932,3372)
  L08 - BOTTOM w6: R80.2@7808.69,3372 v1(7932,3372)
NetJ5_8: J5.8 R81.2 | length 178.6
  L01 - TOP w6: J5.8@7877.43,3328.39 7878.04,3329 v1(7932,3329)
  L08 - BOTTOM w6: R81.2@7808.69,3328 7809.69,3329 v1(7932,3329)
NetJ5_9: J5.9 MD1.W15 R83.2 U16.4 | length 3022.1
  L01 - TOP w6: v1(6200,3714) 6200.31,3714 6233.94,3747.63 MD1.W15@6234.25,3747.63 ; v1(7932,3295) 7987.35,3295 J5.9@7989.63,3297.28 7989.63,3330.65 7962,3358.28 v1(7962,3817) 8027,3817 J5.9@8029,3815
  L03 - SIG w6: v1(6200,3714) 6200,3748 6267,3815 7770.89,3815 7803.89,3782 7927,3782 v1(7962,3817)
  L08 - BOTTOM w6: U16.4@7550.4,3301.8 7550.4,3276.6 7556,3271 7888,3271 7913,3296 7931,3296 v1(7932,3295) ; R83.2@7918.69,3814 7921.69,3817 v1(7962,3817)
NetJ5_10: J5.10 R82.1 | length 315.7
  L01 - TOP w10: R82.1@7402.83,3597.14 7459.46,3597.14 J5.10@7471.91,3584.69 7451.28,3564.06 7451.28,3380.91 J5.10@7471.91,3360.28
NetL1_1: L1.1 U3.5@5684,1468.28 | length 254.4
  L01 - TOP w16: 5684,1422.53 U3.5@5684,1468.28
  L01 - TOP w20: L1.1@5683.65,1214 5684,1214.35 5684,1422.53
NetL2_1: L2.1 U6.5@6037,1361.72 | length 272.6
  L01 - TOP w16: L2.1@6036.35,1634 6037,1633.35 6037,1412.46 U6.5@6037,1361.72
NetMD1_A2: MD1.A2 R128.2 | length 182.2
  L01 - TOP w6: v1(5328.5,4990) 5328.5,4989.01 5364.17,4953.34 MD1.A2@5364.17,4952.36
  L08 - BOTTOM w6: R128.2@5271.62,5074 5309.5,5074 5328.5,5055 v1(5328.5,4990)
NetMD1_A3: MD1.A3 R126.2 | length 114.5
  L01 - TOP w4.25: MD1.A3@5431.1,4952.36 5431.1,4955.23 5464,4988.13 v1(5464,4991)
  L08 - BOTTOM w4.25: v1(5464,4991) 5483.21,4991 5495.5,5003.29 R126.2@5495.5,5028.88
NetMD1_A5: MD1.A5 R122.2 | length 91.2
  L01 - TOP w4.25: MD1.A5@5564.96,4952.36 5564.96,4955.16 5597.5,4987.7 v1(5597.5,4990.5)
  L08 - BOTTOM w4.25: v1(5597.5,4990.5) 5597.5,5029.38 R122.2@5598,5029.88
NetMD1_A11: MD1.A11 R113.2 | length 113.6
  L01 - TOP w4.25: MD1.A11@5966.54,4952.36 5966.54,4953.7 5998.5,4985.66 v1(5998.5,4987)
  L08 - BOTTOM w4.25: R113.2@5967,5029.38 5967,5001 5981,4987 v1(5998.5,4987)
NetMD1_AA16: MD1.AA16 R220.2 | length 293.4
  L01 - TOP w6: MD1.AA16@6301.18,3613.77 6301.18,3612.05 6332.5,3580.73 v1(6332.5,3579)
  L08 - BOTTOM w6: R220.2@6208.62,3427 6260.5,3427 6290.5,3457 6290.5,3557.37 6312.13,3579 v1(6332.5,3579)
NetMD1_AA17: MD1.AA17 R309.1 | length 237.3
  L01 - TOP w6: MD1.AA17@6368.11,3613.77 6368.17,3613.77 6403.44,3578.5 v1(6403.5,3578.5)
  L08 - BOTTOM w6: v1(6403.5,3578.5) 6444.17,3578.5 6494.5,3528.17 R309.1@6494.5,3452.69
NetMD1_AB17: MD1.AB17 R310.1 | length 164.6
  L01 - TOP w6: MD1.AB17@6368.11,3546.84 6368.31,3546.65 6368.31,3513.19 v1(6368.5,3513)
  L08 - BOTTOM w6: v1(6368.5,3513) 6432.09,3513 6456.09,3489 6456.09,3456.78 R310.1@6455.5,3456.19
NetMD1_B3: MD1.B3 R127.2 | length 235.5
  L01 - TOP w6: v1(5399,4920.5) 5399,4919.01 5431.1,4886.91 MD1.B3@5431.1,4885.43
  L08 - BOTTOM w6: R127.2@5272.12,5025.5 5272.12,4996.88 5348.5,4920.5 v1(5399,4920.5)
NetMD1_B4: MD1.B4 R125.2 | length 221.5
  L01 - TOP w4.25: v1(5465.5,4918) MD1.B4@5498.03,4885.43
  L08 - BOTTOM w4.25: R125.2@5363.5,5026.88 5363.5,4978.5 5405,4978.5 v1(5465.5,4918)
NetMD1_B10: MD1.B10 R116.2 | length 196.3
  L01 - TOP w4.25: v1(5866.2,4918.3) 5866.46,4918.3 5899.34,4885.43 MD1.B10@5899.61,4885.43
  L08 - BOTTOM w4.25: R116.2@5804.5,5028.88 5804.5,4957.5 5843.71,4918.29 v1(5866.2,4918.3)
NetMD1_B19: MD1.B19 R306.2 | length 300.9
  L01 - TOP w6: MD1.B19@6501.97,4885.43 6502.45,4885.43 6532.02,4915 v1(6532.5,4915)
  L08 - BOTTOM w6: v1(6532.5,4915) 6712,4915 6740.5,4886.5 R306.2@6778.81,4886.5
NetMD1_C5: MD1.C5 R123.2 | length 233.8
  L01 - TOP w4.25: v1(5531,4850.5) 5531.98,4850.5 5563.98,4818.5 MD1.C5@5564.96,4818.5
  L08 - BOTTOM w4.25: v1(5531,4850.5) 5548.5,4868 R123.2@5548.5,5029.88
NetMD1_C11: MD1.C11 R114.2 | length 232
  L01 - TOP w4.25: v1(5934.5,4850) 5934.77,4850 5966.27,4818.5 MD1.C11@5966.54,4818.5
  L08 - BOTTOM w4.25: R114.2@5915,5028.88 5915,4869.5 v1(5934.5,4850)
NetMD1_D5: MD1.D5 R124.2 | length 346.4
  L01 - TOP w4.25: v1(5532,4783.5) 5532.51,4783.5 5564.45,4751.57 MD1.D5@5564.96,4751.57
  L08 - BOTTOM w4.25: R124.2@5430,5027.38 5430,4992.91 5486.51,4936.39 5486.51,4804.99 5508,4783.5 v1(5532,4783.5)
NetMD1_D11: MD1.D11 R115.2 | length 321.9
  L01 - TOP w4.25: v1(5935,4784) 5935,4783.55 5966.54,4752.02 MD1.D11@5966.54,4751.57
  L08 - BOTTOM w4.25: R115.2@5860,5029.38 5860,4971.27 5898.57,4932.7 5898.57,4820.43 v1(5935,4784)
NetMD1_E10: MD1.E10 R117.2 | length 443
  L01 - TOP w4.25: v1(5867.5,4716) 5867.87,4716 5899.23,4684.64 MD1.E10@5899.61,4684.64
  L08 - BOTTOM w4.25: v1(5867.5,4716) 5868.5,4715 5896,4715 6029,4848 R117.2@6029,5028.88
NetMD1_E19: MD1.E19 R307.2 | length 343.3
  L01 - TOP w6: MD1.E19@6501.97,4684.64 6501.97,4685.05 6535,4718.09 v1(6535,4718.5)
  L08 - BOTTOM w6: v1(6535,4718.5) 6660.5,4844 R307.2@6778.81,4844
NetMD1_K6: MD1.K6 R85.2 | length 2032.6
  L01 - TOP w6: v1(5598.5,4316) 5598.5,4316.3 5631.89,4349.69 MD1.K6@5631.89,4349.99 ; v1(6987.57,4019.61) 6987.57,4016.78 7002.35,4002 7043.81,4002 R85.2@7045.31,4003.5
  L08 - BOTTOM w6: v1(5598.5,4316) 5639.57,4274.93 5639.57,3971.43 5796.05,3814.95 6369.95,3814.95 6435.5,3880.5 6435.5,3980 6475.11,4019.61 v1(6987.57,4019.61)
NetMD1_M18: MD1.M18 R93.1 | length 1298.2
  L01 - TOP w6: MD1.M18@6435.04,4216.14 6435.59,4216.14 6467.45,4248 v1(6468,4248) ; v1(7518,4550) R93.1@7569.32,4550
  L08 - BOTTOM w6: v1(6468,4248) 6499,4217 7185,4217 v1(7518,4550)
NetMD1_N18: MD1.N18 R92.1 | length 1243.4
  L01 - TOP w6: MD1.N18@6435.04,4149.21 6436.12,4149.21 6467.92,4181 v1(6469,4181) ; v1(7531,4349) R92.1@7569.32,4349
  L08 - BOTTOM w6: v1(6469,4181) 6500.79,4149.21 7331.21,4149.21 v1(7531,4349)
NetMD1_T18: MD1.T18 R94.1 | length 1771.2
  L01 - TOP w6: MD1.T18@6435.04,3948.42 6435.04,3946.69 6469,3912.73 v1(6469,3911) ; v1(7517,4599) R94.1@7569.32,4599
  L08 - BOTTOM w6: v1(6469,3911) 6559.77,4001.77 7271.77,4001.77 7652,4382 7652,4492 7545,4599 v1(7517,4599)
NetMD1_T21: MD1.T21 R66.2 | length 178
  L01 - TOP w6: MD1.T21@6635.83,3948.42 6636.7,3948.42 6668.62,3916.5 v1(6669.5,3916.5)
  L08 - BOTTOM w6: v1(6669.5,3916.5) 6690.5,3895.5 R66.2@6791.88,3895.5
NetMD1_U22: MD1.U22 R65.2 | length 104.8
  L01 - TOP w6: MD1.U22@6702.76,3881.49 6702.76,3881.37 6736.5,3847.62 v1(6736.5,3847.5)
  L08 - BOTTOM w6: v1(6736.5,3847.5) 6791.88,3847.5 R65.2@6792.88,3846.5
NetMD1_V17: MD1.V17 R308.2 | length 524.3
  L01 - TOP w6: MD1.V17@6368.11,3814.56 6368.11,3814.48 6401,3781.59 v1(6401,3781.5)
  L08 - BOTTOM w6: v1(6401,3781.5) 6401,3717 6431,3687 6731.71,3687 6751.71,3707 R308.2@6793.38,3707
NetMD1_W18: MD1.W18 R304.2 | length 402.6
  L01 - TOP w6: MD1.W18@6435.04,3747.63 6435.2,3747.63 6468.84,3714 v1(6469,3714)
  L08 - BOTTOM w6: v1(6469,3714) 6500,3745 6688,3745 6728.5,3785.5 6793.38,3785.5 R304.2@6793.88,3785
NetNT4_1: NT4.1 Y1.3 | length 41.8
  L01 - TOP w6: NT4.1@4672,6812.19 Y1.3@4672.03,6854.02
NetNT4_2: NT4.2 R109.1 U22.1 | length 152.6
  L01 - TOP w4.25: R109.1@4612,6746.81 4628.31,6746.81 4654.31,6772.81 NT4.2@4672,6772.81 4673.56,6774.38 4750.32,6774.38 U22.1@4752.33,6776.39
NetQ1_1: Q1.1 Q1.2 Q1.3 Q2.1 Q2.2 Q2.3 U2.8 | length 754.6
  L01 - TOP w10: U2.8@6974.18,863.39 7009.39,863.39 v1(7023,877)
  L08 - BOTTOM w10: v1(6695,592) 6694,591 6632.86,591 6627,596.86 6627,651 6680,704 6871,704 6887,720 6887,866 6898,877 v1(7023,877)
NetQ1_4: Q1.4 Q2.4 R10.1 | length 870.7
  L01 - TOP w10: v1(6689,443) Q1.4@6745,443 ; v1(6694.5,639) 6694.75,639.25 6694.75,683.25 Q2.4@6695,683.5 ; R10.1@7101.62,798 7102,797.62 v1(7102,756)
  L08 - BOTTOM w10: v1(6689,443) 6737.89,443 6749.89,455 6749.89,638.11 6749,639 ; v1(6694.5,639) 6749,639 ; v1(7102,756) 7102,719 7062,679 6789,679 6749,639
NetQ4_1: Q4.1 R250.2 | length 52.2
  L01 - TOP w6: Q4.1@7095.61,6979.7 7095.61,6965.89 7105.5,6956 R250.2@7105.5,6931.62
NetQ4_3: Q4.3 R239.1 | length 41.1
  L01 - TOP w10: Q4.3@7102.5,7005.3 R239.1@7102.5,7046.38
NetQ5_1: Q5.1 R251.2 | length 106
  L01 - TOP w6: Q5.1@6218.61,6983.7 6218.61,6961.89 6243.38,6937.12 R251.2@6292.5,6937.12
NetQ5_3: Q5.3 R232.1 | length 34.1
  L01 - TOP w12: Q5.3@6225.5,7009.3 6225.94,7009.73 6225.94,7042.56 R232.1@6226.38,7043
NetQ6_1: Q6.1 R289.2 | length 40.6
  L01 - TOP w6: R289.2@5965.06,6929.12 Q6.1@5965.06,6969.7
NetQ6_3: Q6.3 R279.1 | length 44.7
  L01 - TOP w10: R279.1@5971,7039.38 5971.75,7038.63 5971.75,6996.05 Q6.3@5972.5,6995.3
NetQ7_1: Q7.1 R290.2 | length 108.5
  L01 - TOP w6: Q7.1@5071.11,6980.2 5071.11,6963.89 5095.88,6939.12 R290.2@5153,6939.12
NetQ7_3: Q7.3 R272.1 | length 48.1
  L01 - TOP w10: Q7.3@5078,7005.8 5082.92,7005.8 5084.81,7007.69 5084.81,7020.31 5090.5,7026 5090.5,7044.62 R272.1@5091.38,7045.5
NetR2_2: R2.2 R4.1 U1.14 | length 108.2
  L01 - TOP w8: U1.14@6033,730.83 6033,689.57 6040.57,682 R2.2@6056.31,682 6056.16,681.84 6056.16,641.84 R4.1@6056,641.68
NetR5_1: R5.1 U1.3 | length 92.6
  L01 - TOP w8: U1.3@6033,908 6033.92,908.92 6033.92,929.92 6053.69,949.68 R5.1@6053.69,992
NetR5_2: R5.2 U1.4 | length 84.4
  L01 - TOP w8: U1.4@6013.31,908 6013.31,920.8 6014.31,921.8 R5.2@6014.31,992
NetR8_2: R8.2 U1.12 | length 46.4
  L01 - TOP w8: U1.12@5993.63,730.83 5994.55,729.91 5994.55,707.45 5998.16,703.84 5998.16,694.53 R8.2@6004,688.69
NetR9_1: R9.1 U2.1 | length 346
  L01 - TOP w6: R9.1@6821.38,661 6785,661 6765,681 6765,846 6782.39,863.39 U2.1@6871.82,863.39 U2.1@6870.2,865
NetR10_2: R10.2 U2.6 | length 86.1
  L01 - TOP w10: U2.6@6974.18,812.2 7014.58,812.2 7028.79,798 R10.2@7054.38,798
NetR11_1: R11.1 R12.2 U2.7 | length 214.4
  L01 - TOP w10: U2.7@6974.18,837.8 7047.8,837.8 7065.38,855.38 R12.2@7109,855.38 7109,851.44 7115.81,844.63 7139.37,844.63 7150.38,833.62 R11.1@7170,833.62
NetR22_1: R22.1 U6.2 | length 56.8
  L01 - TOP w8: R22.1@6037,1261.62 U6.2@6037,1318.41
NetR27_2: R27.2 R38.2 SW1.1 | length 164.8
  L01 - TOP w6: SW1.1@6794,2421.77 6795,2420.77 v1(6795,2330) R38.2@6795,2294.69
  L08 - BOTTOM w6: R27.2@6795,2292.69 v1(6795,2330)
NetR28_2: R28.2 R42.2 SW2.1 | length 165.4
  L01 - TOP w6: R42.2@5790,2294.69 v1(5790,2330) SW2.1@5790,2421.77
  L08 - BOTTOM w6: R28.2@5790,2291.69 v1(5790,2330)
NetR29_2: R29.2 R37.2 SW1.2 | length 163.8
  L01 - TOP w6: SW1.2@6894,2421.77 6895,2420.77 v1(6895,2330) R37.2@6895,2294.69
  L08 - BOTTOM w6: R29.2@6895,2293.69 v1(6895,2330)
NetR30_2: R30.2 R41.2 SW2.2 | length 165.4
  L01 - TOP w6: R41.2@5890,2294.69 v1(5890,2330) SW2.2@5890,2421.77
  L08 - BOTTOM w6: R30.2@5890,2291.69 v1(5890,2330)
NetR31_2: R31.2 R36.2 SW1.3 | length 164.8
  L01 - TOP w6: SW1.3@6994,2421.77 6995,2420.77 v1(6995,2330) R36.2@6995,2293.69
  L08 - BOTTOM w6: R31.2@6995,2293.69 v1(6995,2330)
NetR32_2: R32.2 R40.2 SW2.3 | length 165.4
  L01 - TOP w6: R40.2@5990,2294.69 v1(5990,2330) SW2.3@5990,2421.77
  L08 - BOTTOM w6: R32.2@5990,2291.69 v1(5990,2330)
NetR33_2: R33.2 R35.2 SW1.4 | length 166.8
  L01 - TOP w6: R35.2@7094,2293.69 v1(7094,2330) SW1.4@7094,2421.77
  L08 - BOTTOM w6: v1(7094,2330) 7094,2292.69 R33.2@7095,2291.69
NetR34_2: R34.2 R39.2 SW2.4 | length 166.8
  L01 - TOP w6: R39.2@6090,2294.69 v1(6090,2330) SW2.4@6090,2421.77
  L08 - BOTTOM w6: v1(6090,2330) 6090,2291.69 R34.2@6091,2290.69
NetR43_2: R43.2 R54.2 SW3.1 | length 162.8
  L01 - TOP w6: SW3.1@6294,2421.77 6295,2420.77 v1(6295,2330) R54.2@6295,2294.69
  L08 - BOTTOM w6: R43.2@6295,2294.69 v1(6295,2330)
NetR44_2: R44.2 R58.2 SW4.1 | length 163.2
  L01 - TOP w6: R58.2@5287,2294.69 5288,2295.69 v1(5288,2328) 5288,2420.77 SW4.1@5287,2421.77
  L08 - BOTTOM w6: R44.2@5288,2292.69 v1(5288,2328)
NetR45_2: R45.2 R53.2 SW3.2 | length 163.8
  L01 - TOP w6: SW3.2@6394,2421.77 6395,2420.77 v1(6395,2330) R53.2@6395,2294.69
  L08 - BOTTOM w6: R45.2@6395,2293.69 v1(6395,2330)
NetR46_2: R46.2 R57.2 SW4.2 | length 164.6
  L01 - TOP w6: R57.2@5387,2294.69 5388,2295.69 v1(5388,2328) 5388,2420.77 SW4.2@5387,2421.77
  L08 - BOTTOM w6: v1(5388,2328) 5388,2292.69 R46.2@5389,2291.69
NetR47_2: R47.2 R52.2 SW3.3 | length 163.8
  L01 - TOP w6: SW3.3@6494,2421.77 6495,2420.77 v1(6495,2330) R52.2@6495,2294.69
  L08 - BOTTOM w6: R47.2@6495,2293.69 v1(6495,2330)
NetR48_2: R48.2 R56.2 SW4.3 | length 164.2
  L01 - TOP w6: R56.2@5486,2294.69 v1(5486,2328) 5486,2420.77 SW4.3@5487,2421.77
  L08 - BOTTOM w6: v1(5486,2328) 5486,2292.69 R48.2@5487,2291.69
NetR49_2: R49.2 R51.2 SW3.4 | length 164.2
  L01 - TOP w6: SW3.4@6594,2421.77 6595,2420.77 v1(6595,2330) R51.2@6595,2294.69
  L08 - BOTTOM w6: v1(6595,2330) 6595,2294.69 R49.2@6596,2293.69
NetR50_2: R50.2 R55.2 SW4.4 | length 161.4
  L01 - TOP w6: R55.2@5587,2296.69 v1(5587,2328) SW4.4@5587,2421.77
  L08 - BOTTOM w6: R50.2@5587,2291.69 v1(5587,2328)
NetR61_2: R61.2 U13.2 | length 83
  L01 - TOP w6: R61.2@6679.69,5443 U13.2@6762.73,5443
NetR62_2: R62.2 U12.18 | length 111.4
  L08 - BOTTOM w8: U12.18@7621.68,5197.31 7623,5195.98 7623,5183 7638.69,5167.31 7652.69,5167.31 7678,5142 7697.31,5142 R62.2@7701,5138.31
NetR63_2: R63.2 U13.3 | length 83
  L01 - TOP w6: R63.2@6679.69,5393 U13.3@6762.73,5393
NetR85_1: R85.1 S1.2 | length 72
  L01 - TOP w8: R85.1@7084.69,4003.5 7154.55,4003.5 S1.2@7156.05,4002
NetR95_2: R95.2 U18.4 | length 101
  L01 - TOP w8: U18.4@4573.34,5418.07 4609.87,5418.07 4634.69,5393.26 4635.16,5393.26 4635.42,5393 4652.94,5393 R95.2@4660.75,5385.19
NetR96_2: R96.2 U18.5 | length 92.7
  L01 - TOP w8: U18.5@4573.34,5443.67 4623.04,5443.67 4634.51,5432.19 R96.2@4661.25,5432.19
NetR97_2: R97.2 U18.6 | length 91.8
  L01 - TOP w8: U18.6@4573.34,5469.26 4626.06,5469.26 4635.49,5478.69 R97.2@4661.25,5478.69
NetR98_2: R98.2 U18.7 | length 101.1
  L01 - TOP w8: U18.7@4573.34,5494.85 4614.23,5494.85 4638.26,5518.88 4653.44,5518.88 R98.2@4661.25,5526.69
NetR99_2: R99.2 U19.4 | length 97.7
  L01 - TOP w10: U19.4@4566.14,4232.7 4567.62,4231.23 4602.27,4231.23 4622.7,4210.8 4623.79,4210.8 4629.93,4204.66 4642.57,4204.66 R99.2@4649.38,4197.85
NetR100_2: R100.2 U19.5 | length 89.2
  L01 - TOP w10: U19.5@4566.14,4258.3 4566.35,4258.5 4605,4258.5 4618.98,4244.52 R100.2@4649.46,4244.52
NetR101_2: R101.2 U19.6 | length 87.8
  L01 - TOP w10: U19.6@4566.14,4283.89 4604.39,4283.89 4613.51,4293.01 R101.2@4650.12,4293.01
NetR102_2: R102.2 U19.7 | length 96.1
  L01 - TOP w10: U19.7@4566.14,4309.48 4603.98,4309.48 4627.45,4332.95 4642.87,4332.95 R102.2@4649.68,4339.76
NetR103_2: R103.2 U20.4 | length 112.8
  L01 - TOP w8: U20.4@4566.14,3157.2 4615.22,3157.2 4640.11,3132.31 4657.57,3132.31 R103.2@4665.38,3124.5
NetR104_2: R104.2 U20.5 | length 104
  L01 - TOP w8: U20.5@4566.14,3182.8 4627.7,3182.8 4638,3172.5 R104.2@4665.88,3172.5
NetR105_2: R105.2 U20.6 | length 105.3
  L01 - TOP w8: U20.6@4566.14,3208.39 4626.89,3208.39 4639,3220.5 R105.2@4666.38,3220.5
NetR106_2: R106.2 U20.7 | length 114.8
  L01 - TOP w8: U20.7@4566.14,3233.98 4611.98,3233.98 4639.13,3261.13 4660.01,3261.13 R106.2@4666.88,3268
NetR107_1: R107.1 U22.3 | length 86.9
  L01 - TOP w4.25: R107.1@4667.5,6720.19 4672.52,6725.2 U22.3@4752.33,6725.2
NetR108_1: R108.1 U22.8 | length 63.3
  L01 - TOP w4.25: U22.8@4980.67,6776.39 5043.43,6776.39 R108.1@5043.81,6776
NetR110_1: R110.1 U23.8 | length 64.1
  L01 - TOP w6: R110.1@4120.44,5629.25 4125.9,5634.72 4137.87,5634.72 4141.15,5638 4173.71,5638 U23.8@4178.83,5643.11
NetR111_1: R111.1 U23.5 | length 59.8
  L01 - TOP w6: R111.1@4121.19,5725 4126.3,5719.89 U23.5@4178.83,5719.89
NetR112_1: R112.1 U23.7 | length 58
  L01 - TOP w6: R112.1@4122.44,5664.75 4126.39,5668.7 U23.7@4178.83,5668.7
NetR118_1: R118.1 U24.3 | length 87.4
  L01 - TOP w6: R118.1@4924.5,4748.31 4925.2,4747.61 U24.3@4925.2,4661.17
NetR119_1: R119.1 U24.8 | length 65.5
  L01 - TOP w6: U24.8@4976.39,4432.83 4981.19,4428.03 4981.19,4407.36 4995.07,4393.47 4995.07,4378.73 R119.1@4997.7,4376.11
NetR120_1: R120.1 U24.5 | length 56.6
  L01 - TOP w6: R120.1@4895,4378.19 4899.61,4382.8 U24.5@4899.61,4432.83
NetR121_1: R121.1 U24.7 | length 58.4
  L01 - TOP w6: U24.7@4950.8,4432.83 4950.8,4383.89 R121.1@4957.5,4377.19
NetR129_2: R129.2 U25.2 | length 90.8
  L08 - BOTTOM w8: U25.2@4569.14,5162.16 4616,5162.16 4632.72,5178.88 R129.2@4653,5178.88
NetR130_2: R130.2 U26.2 | length 99.6
  L08 - BOTTOM w10: U26.2@4565.14,3997.16 4609.77,3997.16 4631.85,4019.23 4648.35,4019.23 R130.2@4653.5,4024.38
NetR131_1: R131.1 U25.11 | length 81.3
  L08 - BOTTOM w8: U25.11@4569.14,4931.84 4569.81,4931.17 4649.21,4931.17 R131.1@4649.88,4930.5
NetR132_1: R132.1 U26.11 | length 69.9
  L08 - BOTTOM w10: U26.11@4565.14,3766.84 4565.31,3766.67 4634.71,3766.67 R132.1@4634.88,3766.5
NetR133_1: R133.1 U25.21 | length 133.8
  L08 - BOTTOM w8: R133.1@4218.99,5149.52 4250.98,5149.52 4289.52,5110.98 U25.21@4336.86,5110.98
NetR134_1: R134.1 U26.21 | length 137.4
  L08 - BOTTOM w8: R134.1@4211.58,3984.9 4245.14,3984.9 4284.06,3945.98 U26.21@4332.86,3945.98
NetR135_1: R135.1 U25.20 | length 124.7
  L08 - BOTTOM w8: R135.1@4219.01,5101.9 4244.6,5101.9 4261.12,5085.39 U25.20@4336.86,5085.39
NetR136_1: R136.1 U26.20 | length 128.5
  L08 - BOTTOM w8: R136.1@4211.58,3937.9 4246.02,3937.9 4263.53,3920.39 U26.20@4332.86,3920.39
NetR137_1: R137.1 U25.19 | length 120.5
  L08 - BOTTOM w8: R137.1@4218.75,5054 4222.68,5057.94 4335,5057.94 U25.19@4336.86,5059.8
NetR138_1: R138.1 U26.19 | length 120.3
  L08 - BOTTOM w8: R138.1@4211.63,3890.64 4213.92,3892.94 U26.19@4331,3892.94
NetR139_1: R139.1 U25.18 | length 128.6
  L08 - BOTTOM w8: R139.1@4218.93,5008.54 4244.52,5008.54 4270.19,5034.2 U25.18@4336.86,5034.2
NetR140_1: R140.1 U26.18 | length 132.1
  L08 - BOTTOM w8: R140.1@4211.39,3843.59 4236.98,3843.59 4262.59,3869.2 U26.18@4332.86,3869.2
NetR141_1: R141.1 U25.17 | length 136.9
  L08 - BOTTOM w8: R141.1@4219.11,4962.35 4243.49,4962.35 4289.75,5008.61 U25.17@4336.86,5008.61
NetR142_1: R142.1 U26.17 | length 141.6
  L08 - BOTTOM w8: R142.1@4211.87,3797.22 4216.55,3801.91 4237.46,3801.91 4237.46,3804.37 4276.7,3843.61 U26.17@4332.86,3843.61
NetR143_1: R143.1 U25.16 | length 154.1
  L08 - BOTTOM w8: R143.1@4218.57,4914.89 4242.89,4914.89 4289,4961 4289,4974 4298.02,4983.02 U25.16@4336.86,4983.02
NetR144_1: R144.1 U26.16 | length 163
  L08 - BOTTOM w8: R144.1@4212.32,3751.32 4241.81,3751.32 4246.5,3756 4246.5,3772.91 4291.61,3818.02 U26.16@4332.86,3818.02
  L08 - BOTTOM w10: R144.1@4209.62,3747.5 4209.62,3748.62 R144.1@4212.32,3751.32
NetR157_2: R157.2 U27.2 | length 96.1
  L08 - BOTTOM w8: U27.2@4569.14,4756.24 4569.89,4755.5 4606,4755.5 4628.88,4778.38 R157.2@4655.5,4778.38
NetR158_2: R158.2 U28.2 | length 132.3
  L08 - BOTTOM w8: U28.2@4569.14,3590.16 4615.66,3590.16 4644.07,3618.57 R158.2@4689.68,3618.57
NetR159_1: R159.1 U27.11 | length 69.3
  L08 - BOTTOM w8: U27.11@4569.14,4525.93 4570.43,4527.21 4636.09,4527.21 R159.1@4637.38,4528.5
NetR160_1: R160.1 U28.11 | length 74.3
  L08 - BOTTOM w8: U28.11@4569.14,3359.84 4569.22,3359.92 4643.3,3359.92 R160.1@4643.38,3360
NetR161_1: R161.1 U27.21 | length 137.4
  L08 - BOTTOM w8: R161.1@4215.58,4743.98 4249.14,4743.98 4288.06,4705.06 U27.21@4336.86,4705.06
NetR162_1: R162.1 U28.21 | length 137.4
  L08 - BOTTOM w8: R162.1@4215.58,3577.9 4249.14,3577.9 4288.06,3538.98 U28.21@4336.86,3538.98
NetR163_1: R163.1 U27.20 | length 128.5
  L08 - BOTTOM w8: R163.1@4215.58,4696.98 4250.02,4696.98 4267.53,4679.47 U27.20@4336.86,4679.47
NetR164_1: R164.1 U28.20 | length 128.5
  L08 - BOTTOM w8: R164.1@4215.58,3530.9 4250.02,3530.9 4267.53,3513.39 U28.20@4336.86,3513.39
NetR165_1: R165.1 U27.19 | length 123
  L08 - BOTTOM w8: R165.1@4215.63,4649.73 4217.92,4652.02 4335,4652.02 U27.19@4336.86,4653.88
NetR166_1: R166.1 U28.19 | length 120.3
  L08 - BOTTOM w8: R166.1@4215.63,3483.64 4217.92,3485.94 U28.19@4335,3485.94
NetR167_1: R167.1 U27.18 | length 132.1
  L08 - BOTTOM w8: R167.1@4215.39,4602.68 4240.98,4602.68 4266.59,4628.29 U27.18@4336.86,4628.29
NetR168_1: R168.1 U28.18 | length 132.1
  L08 - BOTTOM w8: R168.1@4215.39,3436.59 4240.98,3436.59 4266.59,3462.2 U28.18@4336.86,3462.2
NetR169_1: R169.1 U27.17 | length 141.6
  L08 - BOTTOM w8: R169.1@4215.87,4556.31 4220.55,4561 4241.46,4561 4241.46,4563.46 4280.7,4602.7 U27.17@4336.86,4602.7
NetR170_1: R170.1 U28.17 | length 141.1
  L08 - BOTTOM w8: R170.1@4216.12,3387.5 4223.93,3395.31 4239.4,3395.31 4280.7,3436.61 U28.17@4336.86,3436.61
NetR171_1: R171.1 U27.16 | length 158.1
  L08 - BOTTOM w8: R171.1@4216.32,4510.4 4245.81,4510.4 4250.5,4515.09 4250.5,4532 4295.61,4577.11 U27.16@4336.86,4577.11
NetR172_1: R172.1 U28.16 | length 160.8
  L08 - BOTTOM w8: R172.1@4215.62,3339.5 4241,3339.5 4250.5,3349 4250.5,3365.91 4295.61,3411.02 U28.16@4336.86,3411.02
NetR185_2: R185.2 U29.2 | length 88.8
  L08 - BOTTOM w10: U29.2@4569.14,2931.66 4609.66,2931.66 4628.88,2950.88 R185.2@4650,2950.88
NetR186_1: R186.1 U29.11 | length 73
  L08 - BOTTOM w8: U29.11@4569.14,2701.34 4569.47,2701.67 4641.55,2701.67 R186.1@4641.88,2702
NetR187_1: R187.1 U29.21 | length 139.5
  L08 - BOTTOM w8: R187.1@4213.47,2919.4 4249.14,2919.4 4288.06,2880.48 U29.21@4336.86,2880.48
NetR188_1: R188.1 U29.20 | length 130.9
  L08 - BOTTOM w8: R188.1@4213.62,2871.5 4214.52,2872.4 4250.02,2872.4 4267.53,2854.89 U29.20@4336.86,2854.89
NetR189_1: R189.1 U29.19 | length 120.3
  L08 - BOTTOM w8: R189.1@4215.63,2825.14 4217.92,2827.44 U29.19@4335,2827.44
NetR190_1: R190.1 U29.18 | length 134.9
  L08 - BOTTOM w8: R190.1@4213.62,2775.5 4216.22,2778.09 4240.98,2778.09 4266.59,2803.7 U29.18@4336.86,2803.7
NetR191_1: R191.1 U29.17 | length 144.4
  L08 - BOTTOM w8: R191.1@4213.62,2727 4221.43,2734.81 4237.4,2734.81 4280.7,2778.11 U29.17@4336.86,2778.11
NetR192_1: R192.1 U29.16 | length 162.9
  L08 - BOTTOM w8: R192.1@4214.12,2679.5 4215.62,2681 4241,2681 4250.5,2690.5 4250.5,2707.41 4295.61,2752.52 U29.16@4336.86,2752.52
NetR199_2: R199.2 U30.2 | length 134.1
  L08 - BOTTOM w10: U30.2@4569.14,2530.16 4608.66,2530.16 4618.13,2539.63 4651.09,2539.63 4667.98,2556.52 R199.2@4667.98,2580.9
NetR200_1: R200.1 U30.11 | length 70.3
  L08 - BOTTOM w8: U30.11@4569.14,2299.84 4569.22,2299.92 4639.3,2299.92 R200.1@4639.38,2300
NetR201_1: R201.1 U30.21 | length 139.5
  L08 - BOTTOM w8: R201.1@4213.47,2517.9 4249.14,2517.9 4288.06,2478.98 U30.21@4336.86,2478.98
